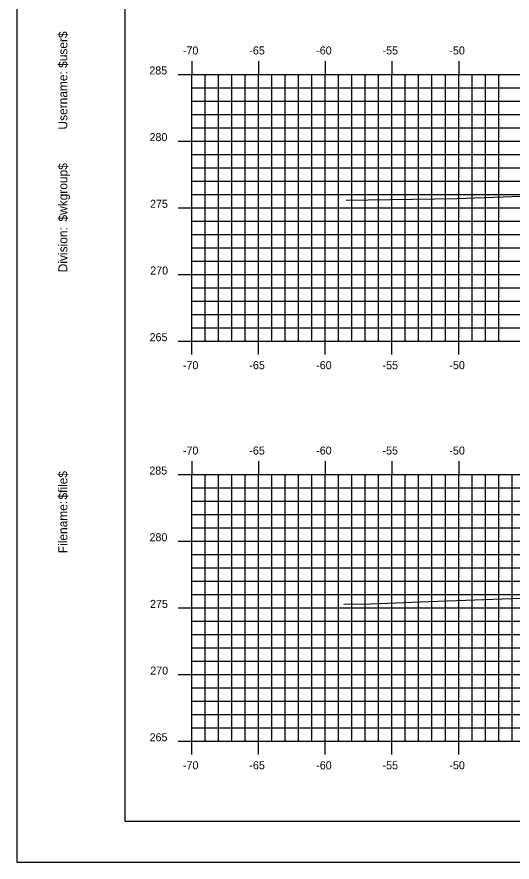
# Model space of a CAD drawing. Extents: x 854231 to 854401, y 366268 to 366378.
# Drawn here: x 854230.7 to 854267.8, y 366268.2 to 366331.6 of the extents above; entities that cross this region are included whole.
import ezdxf

# ---------------------------------------------------------------- set-up
doc = ezdxf.new("R2010")
doc.units = 0
for name, color, linetype in [('BORDER', 7, 'Continuous'), ('H_V ANNOTATION', 7, 'Continuous'), ('MAJOR', 7, 'Continuous'), ('MINOR', 7, 'Continuous'), ('PLOT BOUNDARY', 7, 'Continuous'), ('S_Roadway_Centerline', 7, 'Continuous')]:
    doc.layers.add(name, color=color, linetype=linetype)

msp = doc.modelspace()

# ---------------------------------------------------------------- linework, layer by layer
at = {"layer": 'BORDER'}
for p, q in [((854238.771, 366376.236), (854238.771, 366271.236)), ((854238.771, 366271.236), (854398.771, 366271.236))]:
    msp.add_line(p, q, dxfattribs=at)
at = {"layer": 'MAJOR'}
for p, q in [((854243.771, 366328.238), (854243.771, 366327.236)), ((854248.771, 366328.238), (854248.771, 366327.236)), ((854253.771, 366328.238), (854253.771, 366327.236)), ((854258.771, 366328.238), (854258.771, 366327.236)), ((854263.771, 366328.238), (854263.771, 366327.236)), ((854242.769, 366327.236), (854243.771, 366327.236)), ((854243.771, 366327.236), (854383.771, 366327.236)), ((854243.771, 366307.236), (854243.771, 366327.236)), ((854243.771, 366307.236), (854243.771, 366327.236)), ((854243.771, 366327.236), (854383.771, 366327.236)), ((854248.771, 366307.236), (854248.771, 366327.236)), ((854253.771, 366307.236), (854253.771, 366327.236)), ((854258.771, 366307.236), (854258.771, 366327.236)), ((854263.771, 366307.236), (854263.771, 366327.236)), ((854242.769, 366322.236), (854243.771, 366322.236)), ((854243.771, 366322.236), (854383.771, 366322.236)), ((854242.769, 366317.236), (854243.771, 366317.236)), ((854243.771, 366317.236), (854383.771, 366317.236)), ((854242.769, 366312.236), (854243.771, 366312.236)), ((854243.771, 366312.236), (854383.771, 366312.236)), ((854242.769, 366307.236), (854243.771, 366307.236)), ((854243.771, 366307.236), (854383.771, 366307.236)), ((854243.771, 366307.236), (854383.771, 366307.236)), ((854243.771, 366306.234), (854243.771, 366307.236)), ((854248.771, 366306.234), (854248.771, 366307.236)), ((854253.771, 366306.234), (854253.771, 366307.236)), ((854258.771, 366306.234), (854258.771, 366307.236)), ((854263.771, 366306.234), (854263.771, 366307.236)), ((854243.771, 366298.238), (854243.771, 366297.236)), ((854248.771, 366298.238), (854248.771, 366297.236)), ((854253.771, 366298.238), (854253.771, 366297.236)), ((854258.771, 366298.238), (854258.771, 366297.236)), ((854263.771, 366298.238), (854263.771, 366297.236)), ((854242.769, 366297.236), (854243.771, 366297.236)), ((854243.771, 366297.236), (854383.771, 366297.236)), ((854243.771, 366277.236), (854243.771, 366297.236)), ((854243.771, 366277.236), (854243.771, 366297.236)), ((854243.771, 366297.236), (854383.771, 366297.236)), ((854248.771, 366277.236), (854248.771, 366297.236)), ((854253.771, 366277.236), (854253.771, 366297.236)), ((854258.771, 366277.236), (854258.771, 366297.236)), ((854263.771, 366277.236), (854263.771, 366297.236)), ((854242.769, 366292.236), (854243.771, 366292.236)), ((854243.771, 366292.236), (854383.771, 366292.236)), ((854242.769, 366287.236), (854243.771, 366287.236)), ((854243.771, 366287.236), (854383.771, 366287.236)), ((854242.769, 366282.236), (854243.771, 366282.236)), ((854243.771, 366282.236), (854383.771, 366282.236)), ((854242.769, 366277.236), (854243.771, 366277.236)), ((854243.771, 366277.236), (854383.771, 366277.236)), ((854243.771, 366277.236), (854383.771, 366277.236)), ((854243.771, 366276.234), (854243.771, 366277.236)), ((854248.771, 366276.234), (854248.771, 366277.236)), ((854253.771, 366276.234), (854253.771, 366277.236)), ((854258.771, 366276.234), (854258.771, 366277.236)), ((854263.771, 366276.234), (854263.771, 366277.236))]:
    msp.add_line(p, q, dxfattribs=at)
at = {"layer": 'MINOR'}
for p, q in [((854244.771, 366307.236), (854244.771, 366327.236)), ((854245.771, 366307.236), (854245.771, 366327.236)), ((854246.771, 366307.236), (854246.771, 366327.236)), ((854247.771, 366307.236), (854247.771, 366327.236)), ((854249.771, 366307.236), (854249.771, 366327.236)), ((854250.771, 366307.236), (854250.771, 366327.236)), ((854251.771, 366307.236), (854251.771, 366327.236)), ((854252.771, 366307.236), (854252.771, 366327.236)), ((854254.771, 366307.236), (854254.771, 366327.236)), ((854255.771, 366307.236), (854255.771, 366327.236)), ((854256.771, 366307.236), (854256.771, 366327.236)), ((854257.771, 366307.236), (854257.771, 366327.236)), ((854259.771, 366307.236), (854259.771, 366327.236)), ((854260.771, 366307.236), (854260.771, 366327.236)), ((854261.771, 366307.236), (854261.771, 366327.236)), ((854262.771, 366307.236), (854262.771, 366327.236)), ((854264.771, 366307.236), (854264.771, 366327.236)), ((854265.771, 366307.236), (854265.771, 366327.236)), ((854266.771, 366307.236), (854266.771, 366327.236)), ((854243.771, 366326.236), (854383.771, 366326.236)), ((854243.771, 366326.236), (854244.773, 366326.236)), ((854243.771, 366325.236), (854383.771, 366325.236)), ((854243.771, 366325.236), (854244.773, 366325.236)), ((854243.771, 366324.236), (854383.771, 366324.236)), ((854243.771, 366324.236), (854244.773, 366324.236)), ((854243.771, 366323.236), (854383.771, 366323.236)), ((854243.771, 366323.236), (854244.773, 366323.236)), ((854243.771, 366321.236), (854383.771, 366321.236)), ((854243.771, 366321.236), (854244.773, 366321.236)), ((854243.771, 366320.236), (854383.771, 366320.236)), ((854243.771, 366320.236), (854244.773, 366320.236)), ((854243.771, 366319.236), (854383.771, 366319.236)), ((854243.771, 366319.236), (854244.773, 366319.236)), ((854243.771, 366318.236), (854383.771, 366318.236)), ((854243.771, 366318.236), (854244.773, 366318.236)), ((854243.771, 366316.236), (854383.771, 366316.236)), ((854243.771, 366316.236), (854244.773, 366316.236)), ((854243.771, 366315.236), (854383.771, 366315.236)), ((854243.771, 366315.236), (854244.773, 366315.236)), ((854243.771, 366314.236), (854383.771, 366314.236)), ((854243.771, 366314.236), (854244.773, 366314.236)), ((854243.771, 366313.236), (854383.771, 366313.236)), ((854243.771, 366313.236), (854244.773, 366313.236)), ((854243.771, 366311.236), (854383.771, 366311.236)), ((854243.771, 366311.236), (854244.773, 366311.236)), ((854243.771, 366310.236), (854383.771, 366310.236)), ((854243.771, 366310.236), (854244.773, 366310.236)), ((854243.771, 366309.236), (854383.771, 366309.236)), ((854243.771, 366309.236), (854244.773, 366309.236)), ((854243.771, 366308.236), (854383.771, 366308.236)), ((854243.771, 366308.236), (854244.773, 366308.236)), ((854244.771, 366277.236), (854244.771, 366297.236)), ((854245.771, 366277.236), (854245.771, 366297.236)), ((854246.771, 366277.236), (854246.771, 366297.236)), ((854247.771, 366277.236), (854247.771, 366297.236)), ((854249.771, 366277.236), (854249.771, 366297.236)), ((854250.771, 366277.236), (854250.771, 366297.236)), ((854251.771, 366277.236), (854251.771, 366297.236)), ((854252.771, 366277.236), (854252.771, 366297.236)), ((854254.771, 366277.236), (854254.771, 366297.236)), ((854255.771, 366277.236), (854255.771, 366297.236)), ((854256.771, 366277.236), (854256.771, 366297.236)), ((854257.771, 366277.236), (854257.771, 366297.236)), ((854259.771, 366277.236), (854259.771, 366297.236)), ((854260.771, 366277.236), (854260.771, 366297.236)), ((854261.771, 366277.236), (854261.771, 366297.236)), ((854262.771, 366277.236), (854262.771, 366297.236)), ((854264.771, 366277.236), (854264.771, 366297.236)), ((854265.771, 366277.236), (854265.771, 366297.236)), ((854266.771, 366277.236), (854266.771, 366297.236)), ((854267.771, 366277.236), (854267.771, 366297.236)), ((854243.771, 366296.236), (854383.771, 366296.236)), ((854243.771, 366296.236), (854244.773, 366296.236)), ((854243.771, 366295.236), (854383.771, 366295.236)), ((854243.771, 366295.236), (854244.773, 366295.236)), ((854243.771, 366294.236), (854383.771, 366294.236)), ((854243.771, 366294.236), (854244.773, 366294.236)), ((854243.771, 366293.236), (854383.771, 366293.236)), ((854243.771, 366293.236), (854244.773, 366293.236)), ((854243.771, 366291.236), (854383.771, 366291.236)), ((854243.771, 366291.236), (854244.773, 366291.236)), ((854243.771, 366290.236), (854383.771, 366290.236)), ((854243.771, 366290.236), (854244.773, 366290.236)), ((854243.771, 366289.236), (854383.771, 366289.236)), ((854243.771, 366289.236), (854244.773, 366289.236)), ((854243.771, 366288.236), (854383.771, 366288.236)), ((854243.771, 366288.236), (854244.773, 366288.236)), ((854243.771, 366286.236), (854383.771, 366286.236)), ((854243.771, 366286.236), (854244.773, 366286.236)), ((854243.771, 366285.236), (854383.771, 366285.236)), ((854243.771, 366285.236), (854244.773, 366285.236)), ((854243.771, 366284.236), (854383.771, 366284.236)), ((854243.771, 366284.236), (854244.773, 366284.236)), ((854243.771, 366283.236), (854383.771, 366283.236)), ((854243.771, 366283.236), (854244.773, 366283.236)), ((854243.771, 366281.236), (854383.771, 366281.236)), ((854243.771, 366281.236), (854244.773, 366281.236)), ((854243.771, 366280.236), (854383.771, 366280.236)), ((854243.771, 366280.236), (854244.773, 366280.236)), ((854243.771, 366279.236), (854383.771, 366279.236)), ((854243.771, 366279.236), (854244.773, 366279.236)), ((854243.771, 366278.236), (854383.771, 366278.236)), ((854243.771, 366278.236), (854244.773, 366278.236))]:
    msp.add_line(p, q, dxfattribs=at)
at = {"layer": 'PLOT BOUNDARY'}
msp.add_lwpolyline([(854230.678, 366268.177), (854400.678, 366268.177), (854400.678, 366378.177), (854230.678, 366378.177)], close=True, dxfattribs=at)
at = {"layer": 'S_Roadway_Centerline'}
for points in [[(854255.333, 366317.822), (854263.644, 366317.927), (854271.957, 366318.224)], [(854255.155, 366287.524), (854257.18, 366287.551), (854261.529, 366287.707), (854272.531, 366288.112)]]:
    msp.add_lwpolyline(points, dxfattribs=at)

# ---------------------------------------------------------------- texts
at = {"layer": 'BORDER'}
for s, p in [('$user$', (854234.456, 366327.728)), ('Username:', (854234.456, 366323.104)), ('$wkgroup$', (854234.456, 366316.206)), ('Division:', (854234.456, 366312.403)), ('$file$', (854234.456, 366295.362)), ('Filename:', (854234.456, 366291.335))]:
    msp.add_text(s, height=0.6696, rotation=90, dxfattribs=at).set_placement(p)
at = {"layer": 'H_V ANNOTATION'}
for s, p in [('-70', (854243.112, 366328.736)), ('-65', (854248.088, 366328.736)), ('-60', (854253.096, 366328.736)), ('-55', (854258.067, 366328.736)), ('-50', (854263.075, 366328.736)), ('285', (854240.595, 366327.236)), ('280', (854240.611, 366322.236)), ('275', (854240.649, 366317.236)), ('270', (854240.665, 366312.236)), ('265', (854240.617, 366307.236)), ('-70', (854243.112, 366305.136)), ('-65', (854248.088, 366305.136)), ('-60', (854253.096, 366305.136)), ('-55', (854258.067, 366305.136)), ('-50', (854263.075, 366305.136)), ('-70', (854243.112, 366298.736)), ('-65', (854248.088, 366298.736)), ('-60', (854253.096, 366298.736)), ('-55', (854258.067, 366298.736)), ('-50', (854263.075, 366298.736)), ('285', (854240.595, 366297.236)), ('280', (854240.611, 366292.236)), ('275', (854240.649, 366287.236)), ('270', (854240.665, 366282.236)), ('265', (854240.617, 366277.236)), ('-70', (854243.112, 366275.136)), ('-65', (854248.088, 366275.136)), ('-60', (854253.096, 366275.136)), ('-55', (854258.067, 366275.136)), ('-50', (854263.075, 366275.136))]:
    msp.add_text(s, height=0.6, dxfattribs=at).set_placement(p)

doc.saveas('drawing.dxf')
